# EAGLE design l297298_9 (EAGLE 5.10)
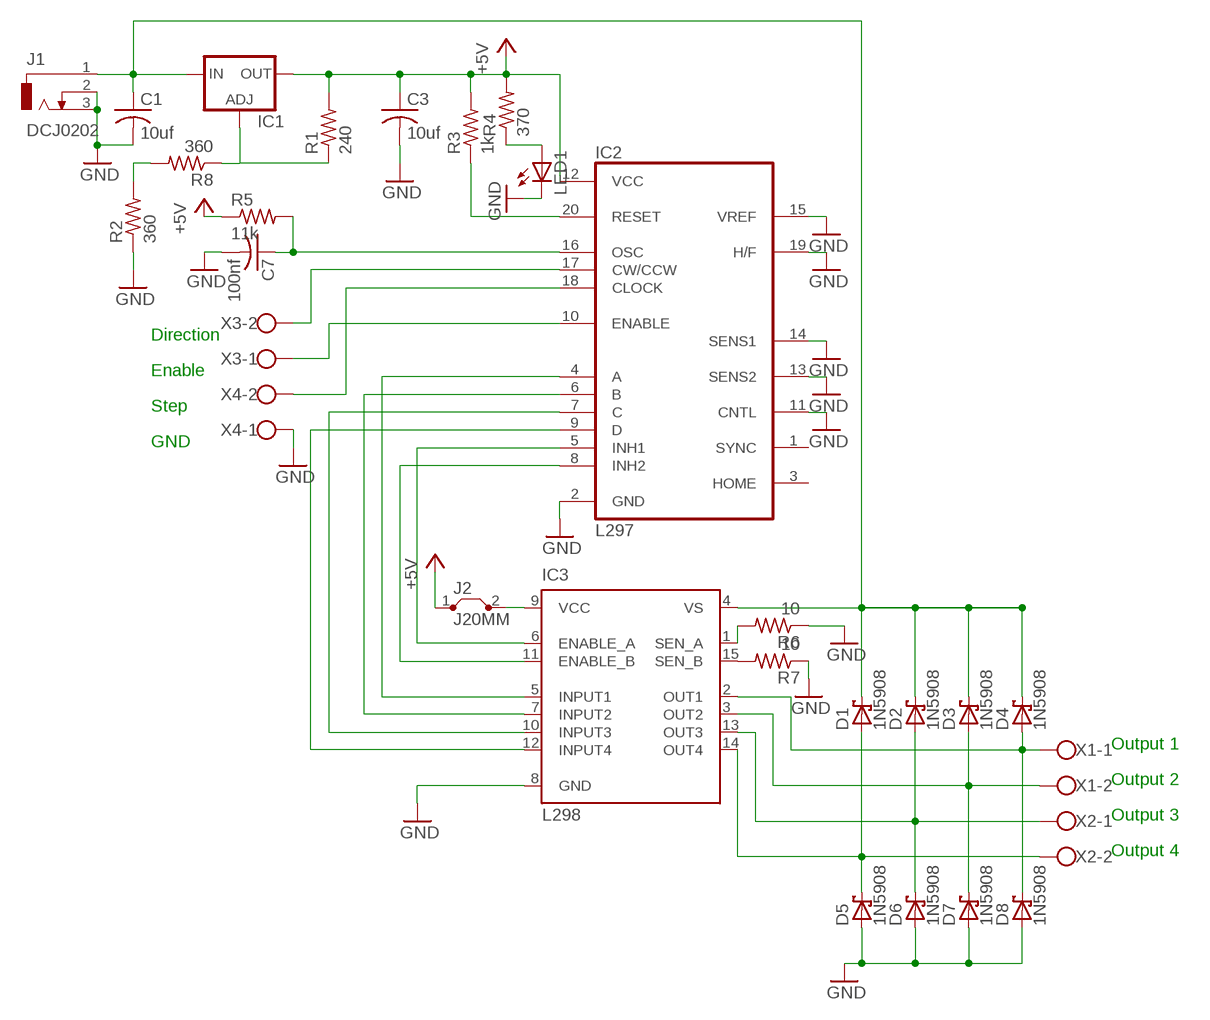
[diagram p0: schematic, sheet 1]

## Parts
C1  10uf  C-US025-060X050  [C025-060X050]
C3  10uf  C-US025-060X050  [C025-060X050]
C7  100nf  C-US025-060X050  [C025-060X050]
D1  1N5908  [C4111-15]
D2  1N5908  [C4111-15]
D3  1N5908  [C4111-15]
D4  1N5908  [C4111-15]
D5  1N5908  [C4111-15]
D6  1N5908  [C4111-15]
D7  1N5908  [C4111-15]
D8  1N5908  [C4111-15]
IC1  LM317TS  [317TS]
IC2  L297  [DIL20]
IC3  L298  [MULTIWATT-15]
J1  DCJ0202  [DCJ0202]
J2  J20MM  [20]
LED1  LED5MM  [LED5MM]
R1  240  R-US_0207/10  [0207/10]
R2  360  R-US_0207/10  [0207/10]
R3  1k  R-US_0207/10  [0207/10]
R4  370  R-US_0207/10  [0207/10]
R5  11k  R-US_0207/10  [0207/10]
R6  10  R-US_0207/10  [0207/10]
R7  10  R-US_0207/10  [0207/10]
R8  360  R-US_0207/10  [0207/10]
X1  W237-02P  [W237-132]
X2  W237-02P  [W237-132]
X3  W237-02P  [W237-132]
X4  W237-02P  [W237-132]

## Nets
+5V: C3.1 IC1.2(OUT) IC2.12(VCC) J2.1 R1.2 R3.2 R4.2 R5.1
GND: C1.2 C3.2 C7.2 D5.A D6.A D7.A D8.A IC2.2(GND) IC2.11(CNTL) IC2.13(SENS2) IC2.14(SENS1) IC2.15(VREF) IC2.19(H/F) IC3.8(GND) J1.2 J1.3 LED1.K(C) R2.1 R6.1 R7.1 X4.1
N$1: IC3.9(VCC) J2.2
N$2: IC1.1(ADJ) R1.1 R8.1
N$3: IC2.5(INH1) IC3.6(ENABLE_A)
N$4: IC2.8(INH2) IC3.11(ENABLE_B)
N$5: IC2.4(A) IC3.5(INPUT1)
N$6: IC2.20(RESET) R3.1
N$7: LED1.A R4.1
N$8: IC2.6(B) IC3.7(INPUT2)
N$9: IC2.7(C) IC3.10(INPUT3)
N$10: C7.1 IC2.16(OSC) R5.2
N$11: IC2.9(D) IC3.12(INPUT4)
N$12: IC3.1(SEN_A) R6.2
N$13: IC3.15(SEN_B) R7.2
N$16: D4.A D8.C IC3.2(OUT1) X1.1
N$17: D3.A D7.C IC3.3(OUT2) X1.2
N$18: D2.A D6.C IC3.13(OUT3) X2.1
N$19: D1.A D5.C IC3.14(OUT4) X2.2
N$20: IC2.17(CW/CCW) X3.2
N$23: IC2.10(ENABLE) X3.1
N$25: IC2.18(CLOCK) X4.2
N$32: C1.1 D1.C D2.C D3.C D4.C IC1.3(IN) IC3.4(VS) J1.1
N$33: R2.2 R8.2
Unconnected: IC2.1(SYNC) IC2.3(HOME)

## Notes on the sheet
- Direction
- Enable
- Step
- GND
- Output 1
- Output 2
- Output 3
- Output 4

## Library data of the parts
C1 C3 C7 = resistor:C-US: CAPACITOR, American symbol
D1-D8 = diode:1N5908: DIODE
IC1 = v-reg:LM317TS: VOLTAGE REGULATOR
IC2 = st-microelectronics:L297: STEPPER MOTOR CONTROLLER
IC3 = st-microelectronics:L298: DUAL FULL-BRIDGE DRIVER
J1 = con-jack:DCJ0202: DC POWER JACK Source: DCJ0202.pdf
J2 = jumper:J: Bridge
LED1 = led:LED: LED
R1-R8 = resistor:R-US_: RESISTOR, American symbol
X1-X4 = con-wago-508:W237-02P: WAGO SREW CLAMP

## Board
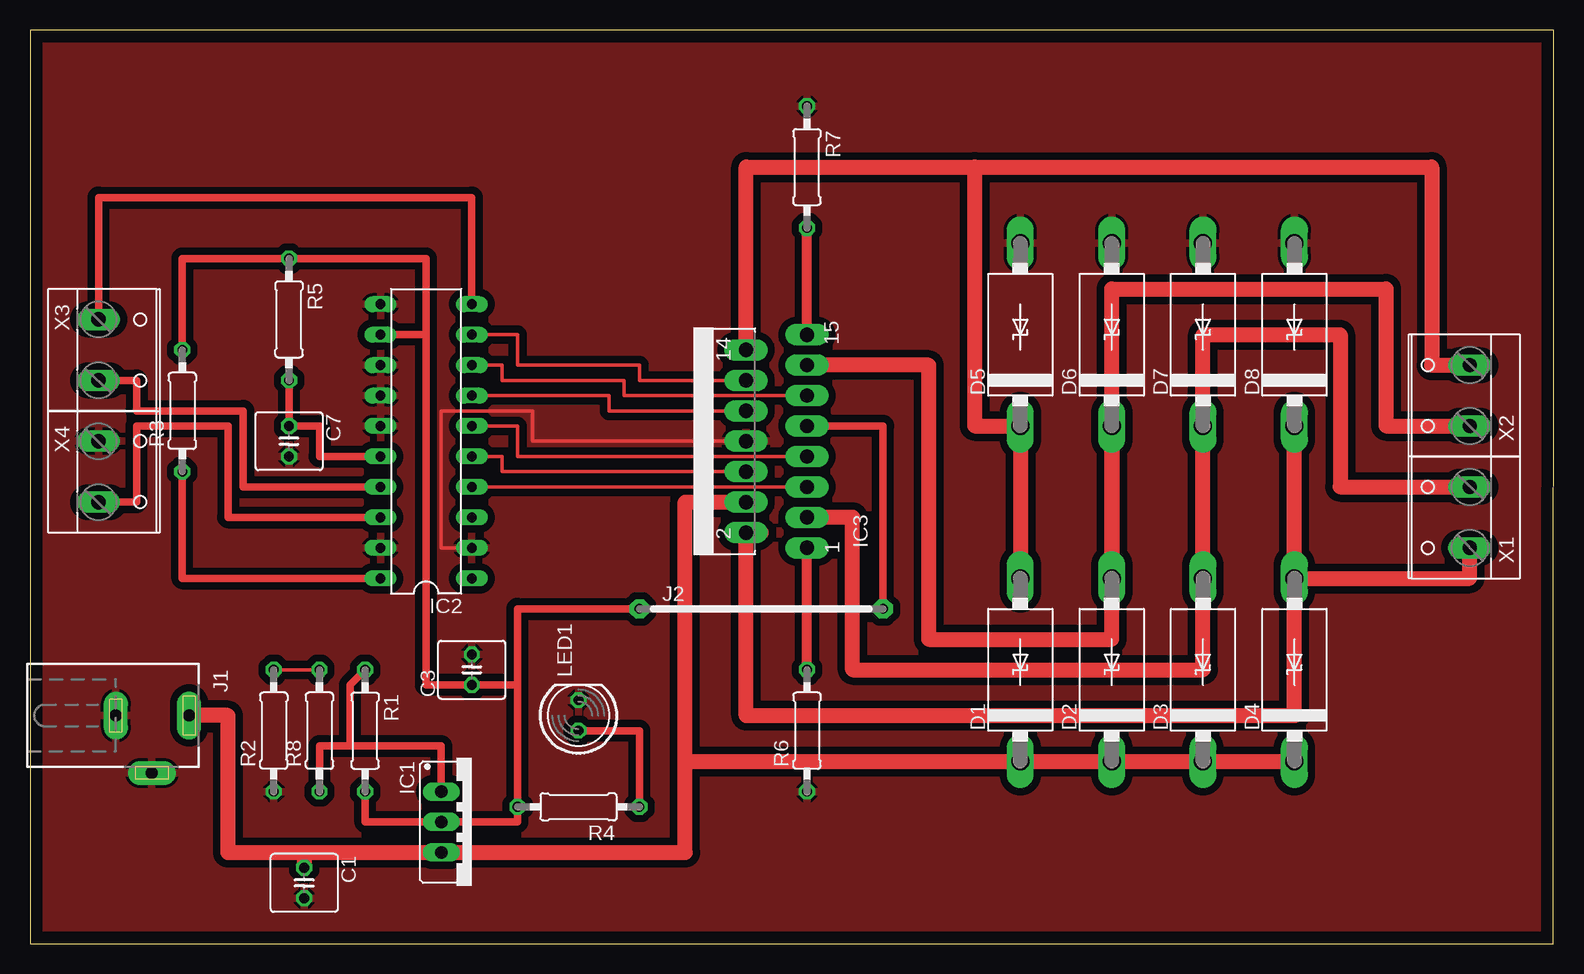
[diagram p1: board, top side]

Size 127 x 76.2 mm. Coordinates in mm from the lower left corner, seen from the top.
Outline: 0,0 126.98,0 127,76.2 0,76.2 0,0
Copper layers (1*16): Top 0.035mm / dielectric 1.5mm / Bottom 0.035mm
Design rules "default": minimum track width 10mil, minimum drill 24mil, track to track 8mil, track to pad 8mil, pad to pad 8mil, via to via 8mil, smd to smd 8mil, copper to edge 40mil, drill to drill 8mil, minimum pad ring 10mil, minimum via ring 8mil, stop-mask expansion 4mil, vias tented up to drill 0mil, thermal gap 10mil

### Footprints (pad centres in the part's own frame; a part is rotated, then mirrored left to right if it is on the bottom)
C025-060X050 = drill 0.813 octagon: 1 -1.27,0; 2 1.27,0
C4111-15 = drill 1.499 long: A 7.62,0; C -7.62,0
317TS = drill 1.016 long: 1 -2.54,-2.54; 2 0,-2.54; 3 2.54,-2.54
DIL20 = drill 0.813 long: 1 -11.43,-3.81; 2 -8.89,-3.81; 3 -6.35,-3.81; 4 -3.81,-3.81; 5 -1.27,-3.81; 6 1.27,-3.81; 7 3.81,-3.81; 8 6.35,-3.81; 9 8.89,-3.81; 10 11.43,-3.81; 11 11.43,3.81; 12 8.89,3.81; 13 6.35,3.81; 14 3.81,3.81; 15 1.27,3.81; 16 -1.27,3.81; 17 -3.81,3.81; 18 -6.35,3.81; 19 -8.89,3.81; 20 -11.43,3.81
MULTIWATT-15 = drill 1.2 long: 1 -8.89,-7.62; 2 -7.62,-2.54; 3 -6.35,-7.62; 4 -5.08,-2.54; 5 -3.81,-7.62; 6 -2.54,-2.54; 7 -1.27,-7.62; 8 0,-2.54; 9 1.27,-7.62; 10 2.54,-2.54; 11 3.81,-7.62; 12 5.08,-2.54; 13 6.35,-7.62; 14 7.62,-2.54; 15 8.89,-7.62
DCJ0202 = drill 1 pad 2 long: 1 0,3.1; 2 4.8,0; 3 0,-3
20 = drill 0.813 pad 1.6 octagon: 1 -10.16,0; 2 10.16,0
LED5MM = drill 0.813 octagon: A -1.27,0; K 1.27,0
0207/10 = drill 0.813 octagon: 1 -5.08,0; 2 5.08,0
W237-132 = drill 1.194 long: 1 -2.54,-0.635; 2 2.54,-0.635

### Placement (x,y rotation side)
C1  22.86,5.08 270 top
C3  36.83,22.86 90 top
C7  21.59,41.91 270 top
D1  82.55,22.86 90 top
D2  90.17,22.86 90 top
D3  97.79,22.86 90 top
D4  105.41,22.86 90 top
D5  82.55,50.8 90 top
D6  90.17,50.8 90 top
D7  97.79,50.8 90 top
D8  105.41,50.8 90 top
IC1  36.83,10.16 270 top
IC2  33.02,41.91 90 top
IC3  57.15,41.91 90 top
J1  10.16,19.05 270 top
J2  60.96,27.94 0 top
LED1  45.72,19.05 90 top
R1  27.94,17.78 270 top
R2  20.32,17.78 90 top
R3  12.7,44.45 90 top
R4  45.72,11.43 180 top
R5  21.59,52.07 270 top
R6  64.77,17.78 90 top
R7  64.77,64.77 270 top
R8  24.13,17.78 90 top
X1  119.38,35.56 90 top
X2  119.38,45.72 90 top
X3  6.35,49.53 270 top
X4  6.35,39.37 270 top

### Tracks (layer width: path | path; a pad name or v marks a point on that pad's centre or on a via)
+5V
  Top 0.61: R1.2 27.94,10.16 IC1.2 40.64,10.16 R4.2 40.64,21.59 | 33.02,50.8 33.02,21.59 C3.1 40.64,21.59 | 33.02,50.8 IC2.12 | 33.02,50.8 33.02,57.15 R5.1 12.7,57.15 R3.2 | J2.1 40.64,27.94 40.64,21.59
GND
  Top 0.305: IC3.8 41.91,41.91 41.91,44.45 34.29,44.45 34.29,33.02 IC2.2
  pour Top (isolate 0.61): 0,76.2 127,76.2 127,0 0,0
N$1
  Top 0.61: J2.2 71.12,43.18 IC3.9
N$2
  Top 0.61: R1.1 26.67,21.59 26.67,16.51 | 26.67,16.51 24.13,16.51 R8.1 | IC1.1 34.29,16.51 26.67,16.51
N$3
  Top 0.305: IC2.5 39.37,40.64 39.37,39.37 IC3.6
N$4
  Top 0.305: IC2.8 39.37,48.26 39.37,46.99 49.53,46.99 49.53,45.72 IC3.11
N$5
  Top 0.305: IC2.4 IC3.5
N$6
  Top 0.61: IC2.20 12.7,30.48 R3.1
N$7
  Top 0.61: R4.1 50.8,17.78 LED1.A
N$8
  Top 0.305: IC2.6 40.64,43.18 40.64,40.64 IC3.7
N$9
  Top 0.305: IC2.7 48.26,45.72 48.26,44.45 IC3.10
N$10
  Top 0.61: R5.2 C7.1 24.13,43.18 24.13,40.64 IC2.16
N$11
  Top 0.305: IC2.9 40.64,50.8 40.64,48.26 50.8,48.26 50.8,46.99 IC3.12
N$12
  Top 0.813: R6.2 IC3.1
N$13
  Top 0.813: IC3.15 R7.2
N$16
  Top 1.27: D4.A D8.C | D4.A 120.02,30.48 X1.1 | 60.96,34.29 IC3.2 59.69,19.05 105.41,19.05 D4.A
N$17
  Top 1.27: X1.2 109.22,38.1 109.22,50.8 97.79,50.8 D7.C D3.A 97.79,22.86 68.58,22.86 68.58,35.56 IC3.3
N$18
  Top 1.27: D6.C D2.A | X2.1 113.03,43.18 113.03,54.61 90.17,54.61 D6.C | D6.C 90.17,25.4 74.93,25.4 74.93,48.26 IC3.13
N$19
  Top 1.27: D1.A D5.C 78.74,43.18 78.74,64.77 | X2.2 116.84,48.26 116.84,64.77 78.74,64.77 | 78.74,64.77 59.69,64.77 IC3.14
N$20
  Top 0.61: IC2.17 17.78,38.1 17.78,44.45 8.89,44.45 8.89,46.99 X3.2
N$23
  Top 0.61: IC2.10 36.83,62.23 5.71,62.23 X3.1
N$25
  Top 0.61: IC2.18 16.51,35.56 16.51,43.18 8.89,43.18 8.89,36.83 X4.2
N$32
  Top 1.27: D4.C D3.C D2.C D1.C 54.61,15.24 | 54.61,15.24 54.61,36.83 IC3.4 | 54.61,15.24 54.61,7.62 IC1.3 22.86,7.62 | 22.86,7.62 16.51,7.62 16.51,19.05 J1.1 | 22.86,7.62 C1.1
N$33
  Top 0.305: R2.2 R8.2

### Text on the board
Pads: Stepper Controller Board v1.0 | PyroElectro.com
